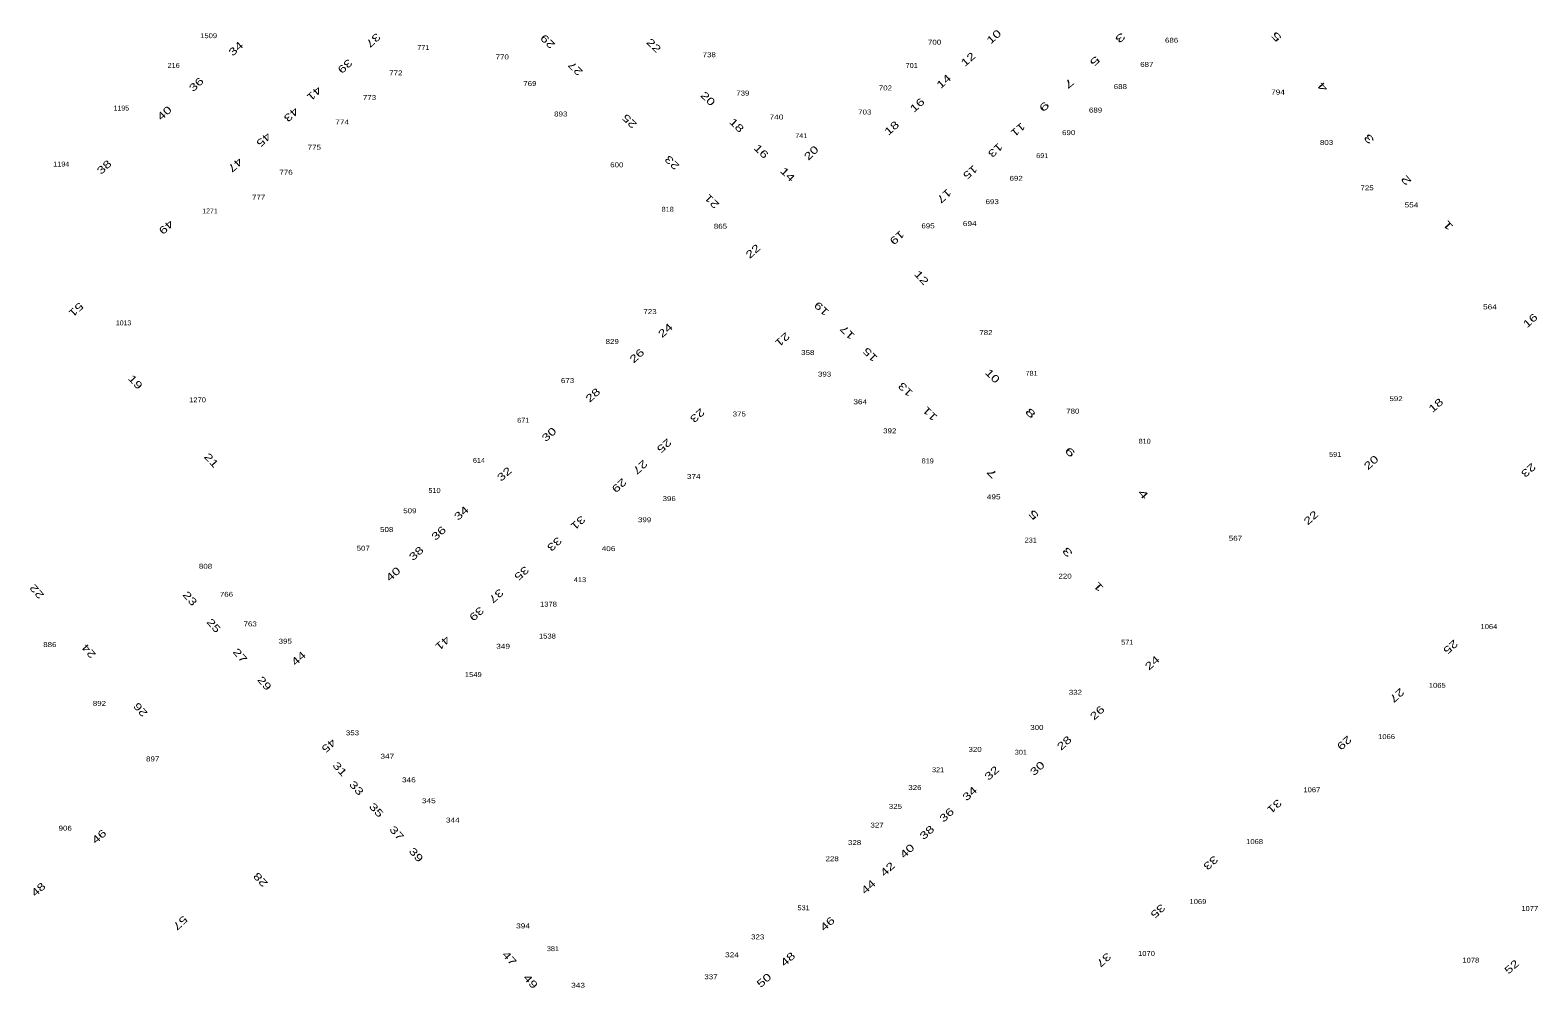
# Model space of a CAD drawing. Extents: x -828673 to -815583, y -1077737 to -1063807.
# Drawn here: x -819544.8 to -819239.5, y -1069308.8 to -1069115 of the extents above; entities that cross this region are included whole.
import ezdxf
from ezdxf.enums import TextEntityAlignment as Align

# ---------------------------------------------------------------- set-up
doc = ezdxf.new("R2010")
doc.units = 0
doc.header["$LTSCALE"] = 0.4
doc.layers.add('1', color=7, linetype='Continuous')
doc.layers.add('2', color=7, linetype='Continuous')

msp = doc.modelspace()

# ---------------------------------------------------------------- texts
at = {"layer": '1'}
for s, width, p in [('1509', 1.15, (-819508.639, -1069116.6)), ('700', 1.2, (-819361.669, -1069117.919)), ('686', 1.2, (-819313.692, -1069117.524)), ('771', 1.1, (-819465.18, -1069118.996)), ('770', 1.2, (-819449.199, -1069120.902)), ('738', 1.2, (-819407.298, -1069120.455)), ('216', 1.1, (-819515.726, -1069122.614)), ('772', 1.2, (-819470.741, -1069124.129)), ('701', 1.1, (-819366.311, -1069122.639)), ('687', 1.2, (-819318.711, -1069122.414)), ('769', 1.2, (-819443.605, -1069126.287)), ('702', 1.2, (-819371.637, -1069127.181)), ('688', 1.2, (-819324.064, -1069126.904)), ('773', 1.2, (-819476.07, -1069129.117)), ('739', 1.2, (-819400.501, -1069128.22)), ('794', 1.25, (-819292.15, -1069128.019)), ('1195', 1.05, (-819526.311, -1069131.255)), ('893', 1.2, (-819437.357, -1069132.45)), ('740', 1.25, (-819393.682, -1069133.057)), ('703', 1.2, (-819375.822, -1069132.053)), ('689', 1.2, (-819329.083, -1069131.66)), ('774', 1.25, (-819481.611, -1069134.077)), ('741', 1.1, (-819388.661, -1069136.838)), ('690', 1.2, (-819334.526, -1069136.227)), ('775', 1.2, (-819487.249, -1069139.182)), ('803', 1.2, (-819282.317, -1069138.219)), ('1194', 1.1, (-819538.478, -1069142.581)), ('600', 1.2, (-819426.009, -1069142.742)), ('691', 1.1, (-819339.878, -1069140.884)), ('776', 1.2, (-819492.975, -1069144.249)), ('692', 1.2, (-819345.164, -1069145.474)), ('725', 1.2, (-819274.121, -1069147.392)), ('1271', 1.05, (-819508.369, -1069152.082)), ('777', 1.2, (-819498.515, -1069149.284)), ('818', 1.1, (-819415.705, -1069151.741)), ('693', 1.2, (-819350.017, -1069150.197)), ('554', 1.25, (-819265.122, -1069150.858)), ('865', 1.2, (-819405.022, -1069155.175)), ('695', 1.2, (-819363.005, -1069155.103)), ('694', 1.25, (-819354.561, -1069154.637)), ('723', 1.2, (-819419.286, -1069172.445)), ('564', 1.25, (-819249.248, -1069171.499)), ('1013', 1.05, (-819525.868, -1069174.736)), ('829', 1.2, (-819426.936, -1069178.499)), ('782', 1.2, (-819351.279, -1069176.694)), ('358', 1.2, (-819387.35, -1069180.733)), ('393', 1.2, (-819383.941, -1069185.098)), ('781', 1.1, (-819342.037, -1069184.943)), ('673', 1.2, (-819435.977, -1069186.404)), ('1270', 1.15, (-819510.897, -1069190.316)), ('364', 1.25, (-819376.725, -1069190.701)), ('592', 1.2, (-819268.246, -1069190.071)), ('671', 1.1, (-819444.954, -1069194.447)), ('375', 1.2, (-819401.216, -1069193.173)), ('780', 1.2, (-819333.693, -1069192.593)), ('392', 1.2, (-819370.753, -1069196.594)), ('810', 1.1, (-819319.144, -1069198.693)), ('614', 1.1, (-819453.916, -1069202.565)), ('819', 1.1, (-819363.063, -1069202.678)), ('591', 1.1, (-819280.583, -1069201.357)), ('374', 1.25, (-819410.433, -1069205.832)), ('510', 1.1, (-819462.919, -1069208.651)), ('495', 1.25, (-819349.712, -1069209.944)), ('509', 1.2, (-819467.904, -1069212.763)), ('396', 1.2, (-819415.396, -1069210.306)), ('399', 1.2, (-819420.383, -1069214.584)), ('508', 1.2, (-819472.597, -1069216.556)), ('231', 1.1, (-819342.217, -1069218.688)), ('567', 1.2, (-819300.764, -1069218.329)), ('507', 1.2, (-819477.343, -1069220.35)), ('406', 1.25, (-819427.682, -1069220.433)), ('808', 1.2, (-819509.273, -1069223.997)), ('413', 1.1, (-819433.463, -1069226.708)), ('220', 1.2, (-819335.264, -1069225.999)), ('766', 1.2, (-819505.031, -1069229.674)), ('1378', 1.15, (-819439.842, -1069231.662)), ('763', 1.2, (-819500.234, -1069235.66)), ('1064', 1.15, (-819249.447, -1069236.205)), ('886', 1.2, (-819540.788, -1069239.847)), ('395', 1.2, (-819493.129, -1069239.162)), ('349', 1.25, (-819449.026, -1069240.193)), ('1538', 1.15, (-819440.054, -1069238.131)), ('571', 1.1, (-819322.672, -1069239.378)), ('1549', 1.15, (-819455.07, -1069245.928)), ('332', 1.2, (-819333.165, -1069249.505)), ('1065', 1.15, (-819259.896, -1069248.098)), ('892', 1.2, (-819530.75, -1069251.753)), ('353', 1.2, (-819479.525, -1069257.707)), ('300', 1.2, (-819340.964, -1069256.625)), ('1066', 1.15, (-819270.178, -1069258.477)), ('320', 1.2, (-819353.47, -1069261.062)), ('301', 1.1, (-819344.209, -1069261.645)), ('897', 1.2, (-819519.965, -1069262.993)), ('347', 1.25, (-819472.462, -1069262.454)), ('346', 1.25, (-819468.099, -1069267.229)), ('321', 1.1, (-819360.967, -1069265.176)), ('326', 1.2, (-819365.657, -1069268.777)), ('1067', 1.15, (-819285.299, -1069269.24)), ('345', 1.25, (-819464.064, -1069271.457)), ('325', 1.2, (-819369.611, -1069272.597)), ('906', 1.2, (-819537.684, -1069277.014)), ('344', 1.25, (-819459.216, -1069275.371)), ('327', 1.2, (-819373.32, -1069276.389)), ('328', 1.2, (-819377.863, -1069279.919)), ('1068', 1.15, (-819296.889, -1069279.722)), ('228', 1.2, (-819382.417, -1069283.193)), ('1069', 1.15, (-819308.365, -1069291.872)), ('531', 1.1, (-819388.198, -1069293.124)), ('1077', 1.15, (-819241.178, -1069293.275)), ('394', 1.25, (-819444.993, -1069296.789)), ('381', 1.1, (-819438.939, -1069301.4)), ('323', 1.2, (-819397.484, -1069299.021)), ('324', 1.25, (-819402.693, -1069302.65)), ('1070', 1.15, (-819318.776, -1069302.379)), ('1078', 1.15, (-819253.116, -1069303.73)), ('337', 1.2, (-819406.943, -1069307.088)), ('343', 1.25, (-819433.846, -1069308.81))]:
    msp.add_text(s, height=1, dxfattribs=dict(at, width=width)).set_placement(p, align=Align.CENTER)
at = {"layer": '2'}
for s, rotation, width, p in [('34', 42.713, 1.4, (-819502.6212, -1069119.2838)), ('37', 222.176, 1.4, (-819475.8224, -1069116.4825)), ('29', 136.01, 1.4, (-819439.4921, -1069116.7487)), ('22', 315.822, 1.4, (-819419.0507, -1069118.6198)), ('10', 41.781, 1.4, (-819349.1782, -1069116.8682)), ('3', 220.752, 1.75, (-819324.5624, -1069115.9774)), ('5', 132.373, 1.75, (-819291.9297, -1069115.823)), ('12', 41.653, 1.4, (-819354.392, -1069121.4458)), ('5', 223.476, 1.75, (-819329.7385, -1069120.7226)), ('39', 222.162, 1.4, (-819481.5216, -1069121.7351)), ('27', 135.745, 1.4, (-819433.8796, -1069122.22)), ('36', 42.096, 1.4, (-819510.6413, -1069126.5233)), ('41', 222.202, 1.4, (-819487.7647, -1069127.2737)), ('14', 41.875, 1.4, (-819359.3126, -1069125.9081)), ('7', 220.045, 1.75, (-819334.904, -1069125.1842)), ('4', 132.265, 1.75, (-819282.6026, -1069125.9794)), ('20', 315.69, 1.4, (-819408.0784, -1069129.3871)), ('16', 42.163, 1.4, (-819364.6914, -1069130.7019)), ('9', 223.307, 1.75, (-819340.0016, -1069129.9107)), ('40', 42.174, 1.4, (-819517.1035, -1069132.3266)), ('43', 222.17, 1.4, (-819492.4185, -1069131.5453)), ('25', 135.669, 1.4, (-819422.9284, -1069132.8843)), ('45', 222.129, 1.4, (-819497.9874, -1069136.6126)), ('18', 315.67, 1.4, (-819402.2656, -1069134.7677)), ('18', 41.696, 1.4, (-819369.8639, -1069135.3501)), ('11', 220.426, 1.35, (-819345.2607, -1069134.5673)), ('16', 315.718, 1.4, (-819397.2996, -1069140.0358)), ('20', 44.904, 1.4, (-819386.1204, -1069140.3621)), ('13', 223.118, 1.4, (-819349.8739, -1069138.7518)), ('3', 132.545, 1.75, (-819273.1836, -1069136.5071)), ('38', 42.263, 1.4, (-819529.2844, -1069143.259)), ('47', 222.218, 1.4, (-819503.7385, -1069141.7332)), ('23', 135.98, 1.4, (-819414.3213, -1069141.2753)), ('14', 315.798, 1.4, (-819391.9474, -1069144.704)), ('15', 220.727, 1.35, (-819354.9387, -1069143.1858)), ('2', 132.34, 1.75, (-819265.6622, -1069144.8756)), ('17', 222.872, 1.4, (-819360.2372, -1069148.0128)), ('21', 135.71, 1.4, (-819406.2583, -1069149.106)), ('49', 221.844, 1.4, (-819517.7292, -1069154.3125)), ('1', 132.358, 1.75, (-819257.1839, -1069154.0423)), ('19', 221.566, 1.4, (-819369.7509, -1069156.4148)), ('22', 41.944, 1.4, (-819397.9428, -1069160.2926)), ('12', 312.243, 1.4, (-819364.8781, -1069165.5743)), ('51', 222.715, 1.4, (-819535.9697, -1069171.0173)), ('19', 137.273, 1.4, (-819384.0641, -1069170.8199)), ('16', 42.155, 1.4, (-819240.5834, -1069174.3241)), ('24', 41.835, 1.4, (-819415.6747, -1069176.3097)), ('17', 135.668, 1.4, (-819378.8214, -1069175.6332)), ('21', 222.023, 1.4, (-819392.9589, -1069177.0532)), ('26', 41.991, 1.4, (-819421.4468, -1069181.4408)), ('15', 135.44, 1.4, (-819374.1948, -1069180.1441)), ('10', 315.665, 1.4, (-819350.4636, -1069185.5148)), ('19', 312.746, 1.4, (-819524.0183, -1069186.6989)), ('28', 41.796, 1.4, (-819430.3554, -1069189.4008)), ('13', 135.948, 1.4, (-819367.0525, -1069187.1859)), ('18', 41.489, 1.4, (-819259.7034, -1069191.4664)), ('23', 221.586, 1.4, (-819410.1807, -1069192.4304)), ('11', 135.4, 1.4, (-819362.1049, -1069192.1045)), ('8', 315.767, 1.75, (-819342.7812, -1069193.0352)), ('30', 41.753, 1.4, (-819439.2359, -1069197.375)), ('25', 222.214, 1.4, (-819416.9156, -1069198.5451)), ('6', 315.985, 1.75, (-819334.7806, -1069200.9305)), ('21', 312.7, 1.4, (-819508.6232, -1069202.5449)), ('27', 222.068, 1.4, (-819421.7705, -1069202.8824)), ('20', 42.365, 1.4, (-819272.7824, -1069203.0422)), ('23', 221.503, 1.4, (-819241.9345, -1069203.5019)), ('32', 41.792, 1.4, (-819448.2753, -1069205.3829)), ('29', 221.813, 1.4, (-819426.023, -1069206.5922)), ('7', 135.55, 1.75, (-819349.5458, -1069204.1696)), ('4', 312.057, 1.75, (-819319.9808, -1069209.3981)), ('34', 41.728, 1.4, (-819456.9882, -1069213.3022)), ('5', 132.258, 1.75, (-819341.0731, -1069212.5969)), ('31', 221.854, 1.4, (-819434.3461, -1069214.1488)), ('22', 42.392, 1.4, (-819284.9791, -1069214.2229)), ('36', 41.586, 1.4, (-819461.5743, -1069217.3626)), ('33', 221.975, 1.4, (-819439.1194, -1069218.4538)), ('38', 41.783, 1.4, (-819466.1082, -1069221.4461)), ('3', 132.224, 1.75, (-819334.2266, -1069220.1545)), ('40', 41.696, 1.4, (-819470.7929, -1069225.6281)), ('35', 221.86, 1.4, (-819445.7725, -1069224.3725)), ('22', 131.172, 1.4, (-819542.8757, -1069228.1262)), ('1', 132.357, 1.75, (-819327.9429, -1069227.1793)), ('23', 311.25, 1.4, (-819512.9856, -1069230.4965)), ('37', 221.745, 1.4, (-819450.9221, -1069228.9568)), ('39', 221.57, 1.4, (-819454.8728, -1069232.5629)), ('25', 311.223, 1.35, (-819508.1604, -1069235.9898)), ('24', 131.145, 1.35, (-819532.3489, -1069240.189)), ('41', 221.513, 1.4, (-819461.7509, -1069238.4918)), ('25', 222.096, 1.4, (-819257.6957, -1069239.2977)), ('27', 311.193, 1.4, (-819502.8348, -1069242.0546)), ('44', 41.894, 1.4, (-819489.9468, -1069242.7145)), ('24', 42.017, 1.4, (-819317.116, -1069243.606)), ('29', 311.222, 1.35, (-819497.9024, -1069247.6788)), ('27', 222.148, 1.4, (-819268.5547, -1069249.0837)), ('26', 131.139, 1.35, (-819521.8908, -1069252.0439)), ('26', 42.803, 1.4, (-819328.2381, -1069253.7052)), ('28', 42.468, 1.4, (-819334.9184, -1069259.8182)), ('29', 222.138, 1.4, (-819279.2233, -1069258.6929)), ('45', 221.285, 1.35, (-819484.8096, -1069259.2579)), ('31', 312.274, 1.4, (-819482.6117, -1069265.0295)), ('32', 42.438, 1.4, (-819349.5851, -1069265.8971)), ('30', 42.129, 1.4, (-819340.3796, -1069264.9594)), ('33', 311.805, 1.4, (-819479.269, -1069268.879)), ('34', 41.92, 1.4, (-819354.0556, -1069270.0743)), ('35', 312.499, 1.4, (-819475.2278, -1069273.3488)), ('36', 42.678, 1.4, (-819358.7209, -1069274.3808)), ('31', 222.077, 1.4, (-819293.3694, -1069271.5426)), ('37', 311.735, 1.4, (-819471.122, -1069278.0017)), ('38', 41.616, 1.4, (-819362.7271, -1069277.9334)), ('46', 41.318, 1.4, (-819530.3367, -1069278.7652)), ('39', 311.696, 1.4, (-819467.1941, -1069282.3951)), ('40', 43.287, 1.4, (-819366.7292, -1069281.6769)), ('33', 222.068, 1.4, (-819306.2605, -1069282.9844)), ('42', 43.241, 1.4, (-819370.6993, -1069285.3427)), ('48', 41.285, 1.35, (-819542.6324, -1069289.4741)), ('28', 131.973, 1.4, (-819497.5997, -1069286.4536)), ('44', 42.277, 1.4, (-819374.5965, -1069288.9486)), ('57', 223.328, 1.4, (-819514.9014, -1069295.1453)), ('46', 41.396, 1.4, (-819382.8849, -1069296.4285)), ('35', 222.057, 1.4, (-819316.9656, -1069292.7451)), ('47', 311.849, 1.4, (-819448.2973, -1069303.3311)), ('48', 41.536, 1.4, (-819390.8913, -1069303.5846)), ('37', 222.036, 1.4, (-819327.9153, -1069302.636)), ('52', 42.129, 1.4, (-819244.3276, -1069305.1314)), ('49', 311.968, 1.4, (-819444.0139, -1069308.023)), ('50', 41.367, 1.4, (-819395.7167, -1069307.8673))]:
    msp.add_text(s, height=1.5, rotation=rotation, dxfattribs=dict(at, width=width)).set_placement(p, align=Align.CENTER)

doc.saveas('drawing.dxf')
